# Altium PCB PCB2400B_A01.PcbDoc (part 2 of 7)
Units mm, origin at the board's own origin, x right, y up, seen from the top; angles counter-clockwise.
Board outline 115 x 60 mm, 6 copper layers (Top Layer, Signal Layer 2, Signal Layer 3, Signal Layer 4, Signal Layer 5, Bottom Layer), stack 1.555 mm thick; 382 components, 308 nets, 1384 pads, 1152 vias.
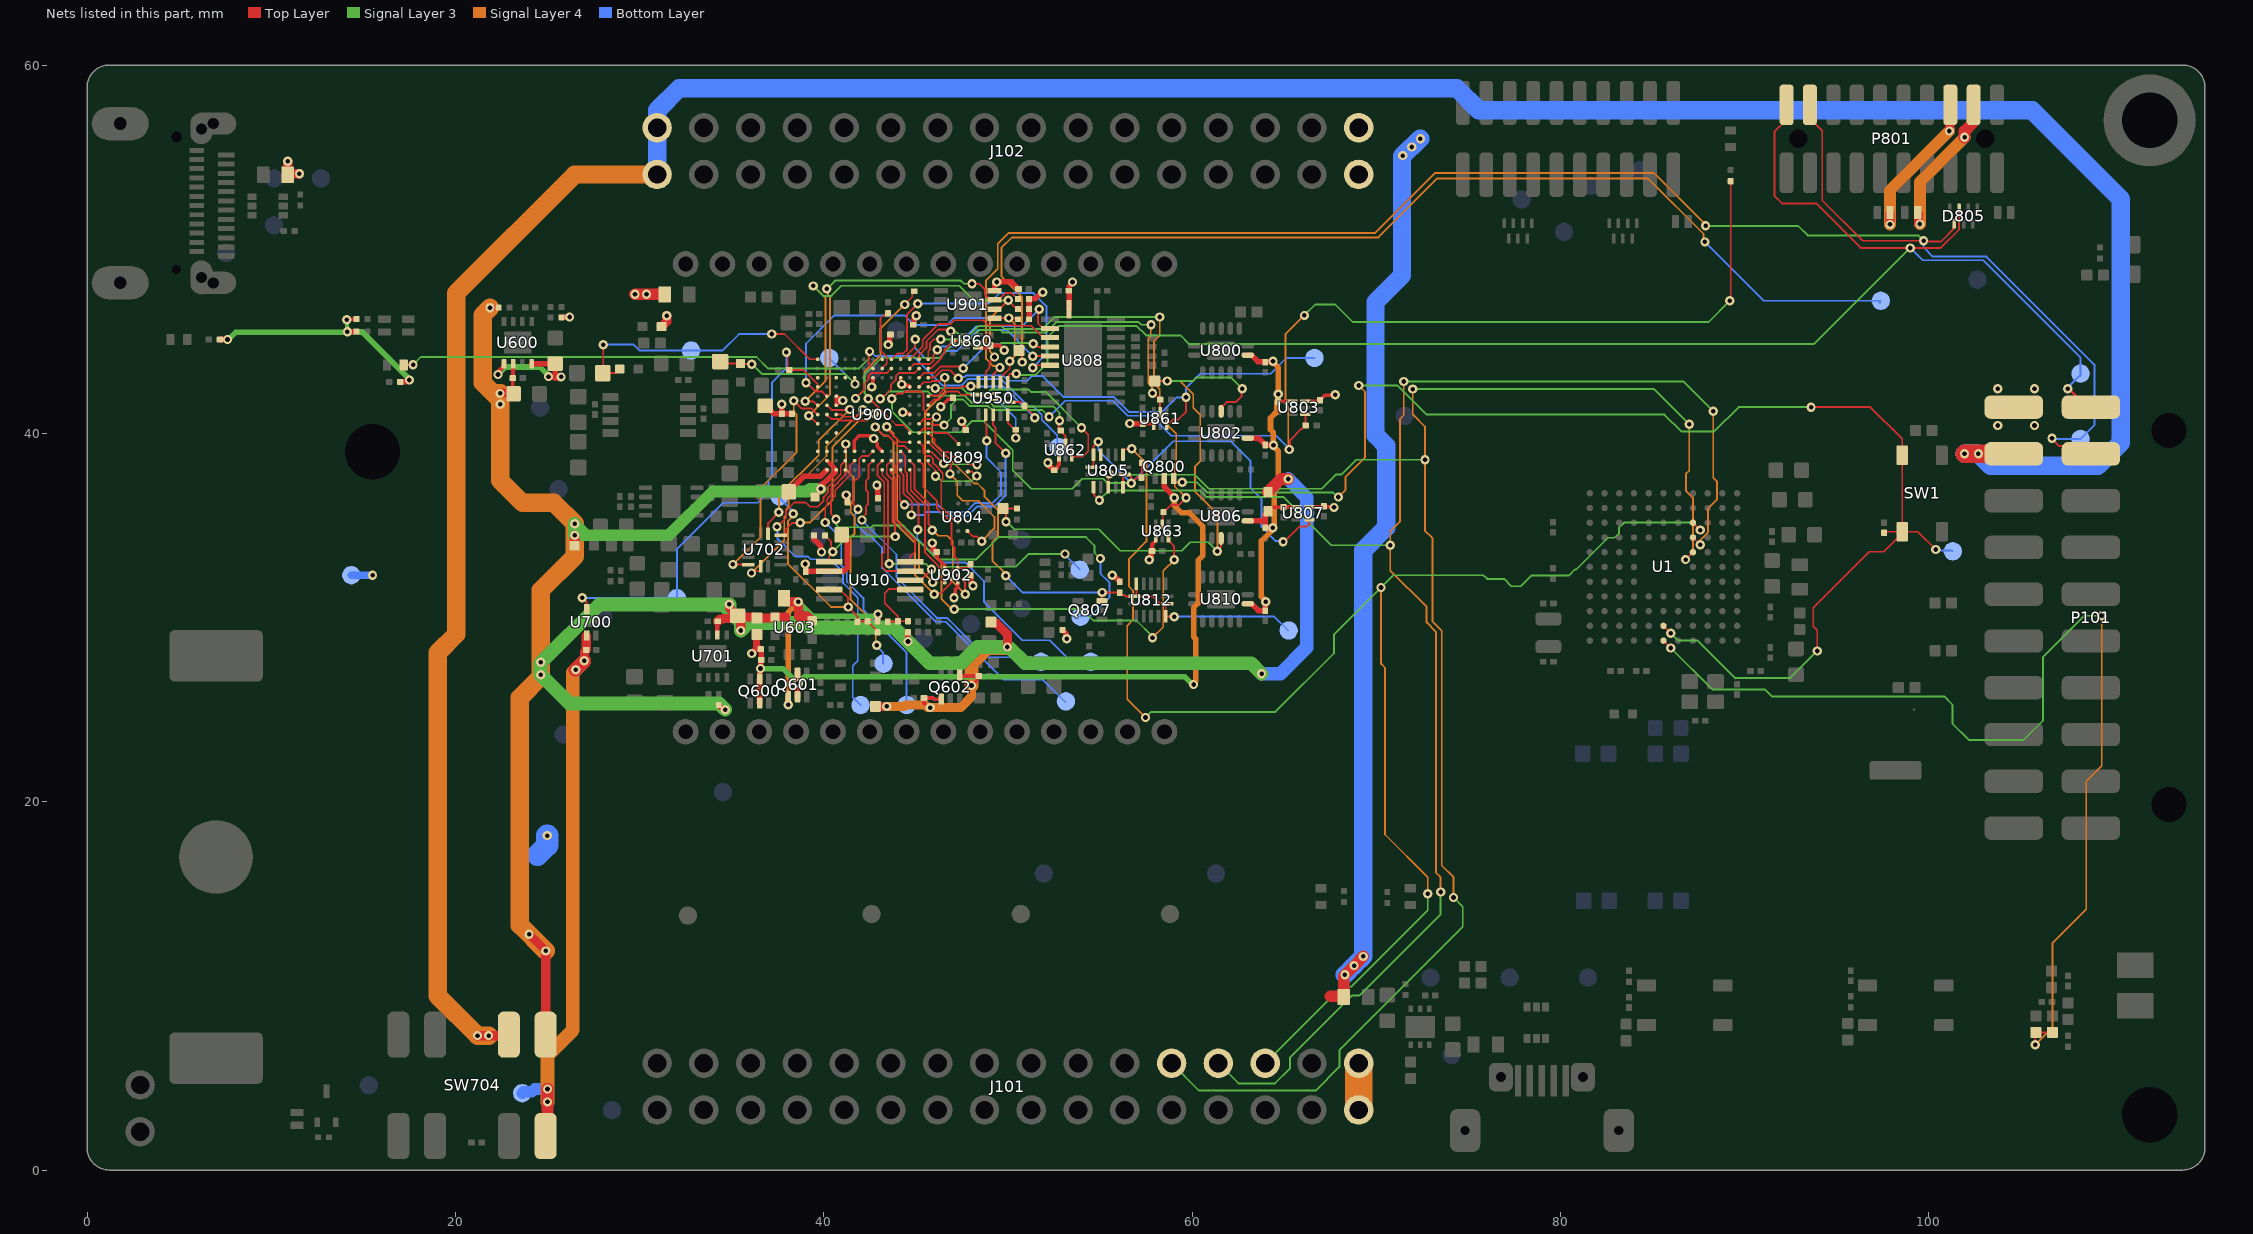
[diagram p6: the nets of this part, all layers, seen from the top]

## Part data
LED100 LED101: library part Yellow
P400: library part USB_MICRO_AB

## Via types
v1: diameter 0.5, hole 0.25, Top Layer to Bottom Layer, tented both sides, 773 vias
v2: diameter 0.508, hole 0.25, Top Layer to Bottom Layer, tented both sides, 379 vias

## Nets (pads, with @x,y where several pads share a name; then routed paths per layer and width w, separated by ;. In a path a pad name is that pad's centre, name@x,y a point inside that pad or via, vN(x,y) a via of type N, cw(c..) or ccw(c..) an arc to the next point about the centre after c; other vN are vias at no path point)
3V3: C607.1 C807.1 C808.1 C860.1 C862.1 C864.1 C866.1 C868.1 C907.1 C908.1 C909.1 C910.1 C911.1 C914.1 C921.1 C922.1 C924.1 C925.1 C926.1 C927.1 C951.1 D807.1 J101.31 J101.32 J102.31 J102.32 L704.1 L900.1 P101.20 P801.3 R601.2 R838.2 R840.2 R903.1 R906.2 R907.1 R908.1 R909.1 R912.1 R919.1 R920.1 R982.1 TPJ600.1 TPJ950.1 U600.1 U600.4 U803.6 U807.6 U808.1 U860.1 U861.1 U862.1 U863.1 U900.C6 U900.C9 U900.G3 U900.H11 U900.J11 U900.K3 U900.L4 U900.L7 U901.8 U902.A1 U902.E3 U910.2 | length 72.9
  Top Layer w0.2: v1(14.098,46.17) 14.12,46.192 14.599,46.192 R920.1@14.622,46.215 ; v2@40.8,41.775 40.8,41.65 U900.H11@40.675,41.525 U900.J11@40.675,42.025 40.72,42.025 40.958,41.787 v2(41.042,41.787) ; U900.C9@41.675,39.025 41.657,39.043 41.657,39.608 41.917,39.868 42.499,39.868 42.617,39.75 v2@42.725,39.75 ; v2(42.6,42.525) 42.659,42.584 42.659,42.802 42.675,42.818 U900.L7@42.675,43.025 ; v2(42.725,39.725) 42.725,39.642 42.904,39.462 42.904,39.296 U900.C6@43.175,39.025 ; v2(43.494,44.826) v2@43.553,44.885 ; U900.L4@44.175,43.025 44.175,42.719 v2(44.233,42.661) ; v2(44.3,41.15) 44.359,41.091 44.609,41.091 U900.G3@44.675,41.025 ; v2@44.3,42.65 44.348,42.602 44.598,42.602 U900.K3@44.675,42.525 ; C914.1@46.128,33.565 46.154,33.539 46.154,33.249 46.573,32.83 46.573,32.702 U902.A1@46.575,32.7 ; v2(46.356,41.455) 46.756,41.855 46.951,41.855 47.011,41.915 C911.1@47.011,41.935 ; v2(47.075,31.069) 47.134,31.069 47.134,31.517 47.273,31.656 47.273,31.898 U902.E3@47.275,31.9 ; v2(47.486,40.664) 47.486,40.581 47.625,40.442 47.625,40.236 47.685,40.176 C909.1@47.705,40.176 ; U860.1@48.374,44.659 48.954,44.659 49.05,44.755 C862.1@49.05,44.775 49.539,44.775 49.805,44.509 v2(49.811,44.509) ; C860.1@52.525,38 52.545,38 52.695,38.15 52.695,38.219 52.775,38.299 U862.1@52.775,38.75 ; C864.1@57.325,40.525 57.925,40.525 U861.1@57.925,40.45 ; C866.1@57.825,33.625 57.825,33.975 58.025,34.175 U863.1@58.025,34.35 ; U803.6@66.15,41.75 66.9,41.75 C807.1@66.95,41.8 66.95,41.82 67.01,41.88 67.03,41.88 67.225,42.075 67.75,42.075 v1(67.775,42.1) ; U807.6@66.38,36.01 67.126,36.01 C868.1@67.162,36.045 67.193,36.014 67.675,36.014 v1(67.707,35.982)
  Top Layer w0.254: v1(22.313,43.198) 22.36,43.245 22.36,43.383 22.637,43.659 U600.1@22.637,43.78
  Top Layer w0.3: C907.1@36.825,41.4 36.95,41.4 37.275,41.075 C924.1@37.725,41.075 ; v2(37.725,41.575) C924.1@37.725,41.075 ; C925.1@38.275,41.075 C924.1@37.725,41.075 ; v2(38.989,32.909) 39.015,32.883 39.015,32.51 C922.1@39.025,32.5 ; C922.1@39.025,32.515 39.035,32.525 41.099,32.525 41.275,32.701 41.275,34.175 C921.1@41,34.45 ; R982.1@39.471,34.452 39.481,34.452 39.491,34.442 39.491,34.231 39.837,33.885 39.837,33.601 v2(39.877,33.562) ; v2(42.889,37.179) 42.882,37.179 42.882,37.162 42.94,37.104 C926.1@42.94,36.453 ; v2@43.5,44.826 v2(43.494,44.826) 43.494,44.882 43.597,44.985 43.597,45.368 43.607,45.378 C910.1@43.627,45.378 ; C908.1@44.889,45.9 44.899,45.91 44.899,46.211 45.027,46.339 v2(45.027,46.395) ; v2(45.886,34.05) 45.875,34.05 45.875,33.994 v2@45.92,33.949 ; R906.2@47.974,32.298 47.984,32.288 47.984,31.901 48.103,31.783 v2(48.103,31.727) ; U901.8@49.275,47.75 49.275,48.1 v2(49.4,48.225) 50.2,48.225 C951.1@50.575,47.85 ; R908.1@51.15,46.2 R907.1@51.15,46.75 R909.1@51.15,47.3 51.16,47.31 51.479,47.31 51.844,47.675 v2(51.9,47.675) ; v2(52.175,38.4) 52.215,38.36 52.215,38.26 52.253,38.222 52.283,38.222 52.505,38 C860.1@52.525,38 ; R838.2@52.975,29.325 52.985,29.315 52.985,29.305 53.16,29.13 53.16,28.89 v2(53.2,28.85) ; U808.1@53.325,46.745 53.325,47.725 C808.1@53.3,47.75 53.32,47.75 53.33,47.76 53.33,47.988 53.511,48.169 v2(53.511,48.225) ; v2(55.675,32.3) 55.715,32.26 55.775,32.26 56.075,31.96 R840.2@56.075,31.95 ; v2(56.615,40.537) 56.621,40.531 57.319,40.531 C864.1@57.325,40.525 ; v2(57.675,33.143) 57.675,33.156 57.795,33.276 57.795,33.615 57.805,33.625 C866.1@57.825,33.625
  Top Layer w0.305: R903.1@7.2,45.1 v1(7.625,45.1) ; v1(14.133,45.521) 14.138,45.526 14.617,45.526 R919.1@14.622,45.531 ; R912.1@17,42.8 17.008,42.808 17.355,42.808 17.447,42.9 v1(17.5,42.9) ; U600.4@24.137,43.78 25.28,43.78 C607.1@25.3,43.8 ; v1(25.056,43.089) 25.094,43.051 25.367,43.051 25.412,43.006 ; C607.1@25.387,43.78 C607.1@25.412,43.78 ; 25.425,42.993 25.412,43.006 ; C607.1@25.437,43.78 C607.1@25.412,43.78 ; v1(25.74,43.071) 25.703,43.033 25.438,43.033 25.412,43.006 ; R601.2@25.762,46.305 25.769,46.313 26.188,46.313 v1(26.2,46.325) ; v2(41.22,36.659) 41.22,36.604 41.292,36.531 41.292,36.283 C927.1@41.3,36.275 ; v2(45.886,34.05) 45.925,34.011 45.925,33.748 46.108,33.565 C914.1@46.128,33.565 ; 25.412,43.006 C607.1@25.412,43.78
  Top Layer w0.5: L704.1@31.2,45.8 31.475,46.075 v2(31.475,46.4) ; D807.1@99.45,51.9 99.45,51.45 v1(99.525,51.375)
  Top Layer w0.635: v2(29.75,47.55) v2(30.375,47.55) L900.1@31.36,47.55 ; v2(101.95,56.075) 101.95,56.419 102.381,56.851 102.381,57.778 P801.3@102.445,57.841
  Signal Layer 3 w0.102: J101.32@69.05,5.725 J101.32@69.15,5.825
  Signal Layer 3 w0.2: v1(14.098,46.17) 14.115,46.152 14.115,45.539 v1(14.133,45.521)
  Signal Layer 3 w0.305: v1@7.625,45.05 7.628,45.05 8.078,45.5 14.133,45.5 14.3,45.5 14.289,45.51 14.939,45.51 17.55,42.9 v1@17.575,42.9 ; v1(22.313,43.198) 22.72,43.605 24.593,43.605 25.056,43.141 v1(25.056,43.089)
  Signal Layer 4 w0.635: v1(99.525,51.375) 99.525,53.65 v2(101.95,56.075)
  Signal Layer 4 w1.5: J101.31@69.05,3.262 J101.32@69.05,5.725
  Bottom Layer w0.4: TPJ600.1@14.35,32.301 15.499,32.301 v1(15.5,32.3)
  Bottom Layer w1.2: TPJ950.1@24.449,17.1 24.984,17.635 v1(24.984,18.162)
  other v1: 103.747,40.43 105.747,40.43 103.747,42.43 105.747,42.43
3V6_SW: C608.1 L702.1 Q601.1 R639.2 U603.B1 | length 14.4
  Top Layer w0.2: U603.B1@38.625,29.65 38.625,30.075
  Top Layer w0.3: Q601.1@38.075,25.7 v2(38.077,25.264) v2(38.077,25.264) ; R639.2@42.925,29.8 42.935,29.81 42.935,30.104 42.97,30.139 42.933,30.175 v2(42.947,30.189)
  Top Layer w0.5: L702.1@37.84,31.05 37.84,30.945 37.925,30.86 38.613,30.86 38.623,30.85 v2(38.625,30.85) 38.625,30.075 39.125,30.075 C608.1@39.375,29.825
  Signal Layer 3 w0.3: v2(38.625,30.85) 39.393,30.082 42.801,30.082 42.914,30.195 42.933,30.175 v2(42.947,30.189)
  Signal Layer 4 w0.3: v2(38.077,25.264) 38.077,30.302 v2(38.625,30.85)
3V6_SW_SENSE: C641.1 R639.1 R640.2 TP923.1 U910.4 | length 12.5
  Top Layer w0.1: U910.4@40.3,31.525 40.875,31.525 41.325,31.075 v2(41.325,30.575) 41.825,30.075 C641.1@41.825,29.775 41.838,29.787 42.363,29.787 R640.2@42.375,29.8 42.375,29.79 42.815,29.35 42.815,29.31 R639.1@42.925,29.2
  Signal Layer 4 w0.1: v1(38.35,35.636) 38.35,35.53 38.057,35.237 38.057,32.918 40.4,30.575 v2(41.325,30.575)
  Bottom Layer w0.1: TP923.1@37.6,36.575 37.6,36.487 38.375,35.712 38.375,35.7 38.375,35.661 v1(38.35,35.636)
5V: C600.1 C609.1 C611.1 C673.1 C674.1 C702.1 C703.1 C901.1 D806.1 L402.1 L600.2 L700.1 L800.1 P801.5 Q602.1 Q602.4 R600.2 R622.2 R633.2 R681.2 R690.2 R700.2 SW704.8 U600.2 U603.A2 U603.B2 U701.2 U900.A11 U900.B12 | length 222.3
  Top Layer w0.2: C611.1@23.1,42.2 23.145,42.155 C611.1@23.162,42.155 ; C600.1@23.112,43.005 23.112,42.238 C611.1@23.15,42.2 ; C600.1@23.125,43.025 23.124,43.026 23.124,43.768 U600.2@23.137,43.78 ; C702.1@34.225,29.775 C702.1@34.25,29.8 ; 37.925,30.025 38.106,29.844 38.106,29.777 38.225,29.658 U603.A2@38.225,29.25 ; C901.1@39.525,36.55 39.775,36.8 39.775,36.934 v2(39.834,36.993) ; U900.B12@40.175,38.525 40.325,38.375 40.325,38.35 ; C674.1@45.506,25.572 C674.1@45.446,25.632 ; v1(45.788,25.111) 45.707,25.111 45.459,25.359 45.447,25.359 C674.1@45.446,25.632 ; Q602.1@46.365,25.565 46.005,25.565 45.938,25.632 C674.1@45.446,25.632 C674.1@45.446,25.632 ; Q602.4@47.375,26.875 47.421,26.829 C673.1@48.404,26.829 ; v1(48.025,26.311) 48.344,26.63 48.344,26.769 C673.1@48.404,26.829 ; C673.1@48.424,26.829 C673.1@48.404,26.829
  Top Layer w0.25: U701.2@34.225,29.05 C702.1@34.225,29.775 ; 40.325,38.375 40.625,38.075 U900.A11@40.625,38
  Top Layer w0.3: v1(21.875,46.825) 21.878,46.828 22.334,46.828 R600.2@22.337,46.83 ; R700.2@34.3,25.25 34.3,25.24 34.499,25.041 34.609,25.041 v2(34.649,25.001) ; 40.167,37.457 40.172,37.457 ; U900.A11@40.625,37.975 40.625,37.909 40.172,37.457 ; v2(44.575,28.7) R633.2@44.575,29.2 ; v2@39.874,37.089 39.874,37.22 39.929,37.275 39.991,37.275 40.172,37.457 ; v2@39.874,37.089 39.874,37.033 v2(39.834,36.993) 39.834,37.049 v2@39.874,37.089
  Top Layer w0.5: v1(10.9,54.775) 10.9,54.06 L600.2@10.89,54.05 10.94,54.1 v1(11.525,54.1) ; v1(22.425,42.175) 22.45,42.2 C611.1@23.1,42.2 ; v1(24,12.8) v1(24.9,11.9) SW704.8@24.9,7.35 SW704.8@24.9,7.25 ; L700.1@26.475,33.9 v2(26.475,34.475) ; C702.1@34.25,29.8 34.375,29.925 34.558,29.925 34.583,29.95 35.175,29.95 C703.1@35.325,30.1 ; v2(34.875,30.725) 34.877,30.723 34.877,30.523 35.3,30.1 C703.1@35.325,30.1 ; v2(35.5,29.3) 35.498,29.302 35.498,29.95 C703.1@35.423,30.025 ; 37.925,30.025 C609.1@37.35,30.025 37.3,29.975 R622.2@36.375,29.975 36.325,30.025 C703.1@35.423,30.025 ; R681.2@42.8,25.175 v1(43.425,25.175) ; R690.2@49.075,29.75 49.125,29.7 49.365,29.7 49.973,29.092 49.973,28.402 v2(49.975,28.4) ; v1(97.9,51.35) D806.1@97.9,51.931 ; v1(101.125,56.425) 101.141,56.441 101.141,57.807 P801.5@101.175,57.841 ; C703.1@35.325,30.1 35.4,30.025 C703.1@35.423,30.025 ; C703.1@35.325,30.1 35.348,30.1 C703.1@35.423,30.025
  Top Layer w0.635: L800.1@64.125,36.825 64.825,37.525 v2(65.225,37.525) ; 67.518,9.432 68.217,9.432 L402.1@68.235,9.414 ; L402.1@68.235,9.4 L402.1@68.235,9.414 ; v1(69.3,11.6) v1(68.8,11.1) 68.235,10.535 L402.1@68.235,9.414
  Signal Layer 3 w0.635: v2(26.475,34.475) 27.1,34.475 ; v2(26.475,35.1) 27.1,34.475 ; v2(39.834,36.993) 39.251,36.993 39.107,36.849 33.969,36.849 31.595,34.475 27.1,34.475
  Signal Layer 3 w0.75: v2(26.475,34.475) v2(26.475,35.1) ; v2(34.649,25.001) 34.315,25.335 26.19,25.335 v2(24.625,26.9) 24.625,27.525 27.807,30.708 34.515,30.708 ; v2@34.875,30.708 34.515,30.708 ; v2(34.875,30.725) 34.875,30.347 ; v2(49.975,28.4) 48.35,28.4 47.475,27.525 45.75,27.525 v2(44.575,28.7) 43.818,29.457 39.134,29.457 38.891,29.7 35.9,29.7 ; v2@50.1,28.35 50.925,27.525 63.2,27.525 v2(63.775,26.95) ; 34.515,30.708 34.875,30.347 ; 34.875,30.347 35.5,29.722 35.5,29.7 ; 35.5,29.7 35.9,29.7 ; 35.5,29.7 v2(35.5,29.3) 35.9,29.7
  Signal Layer 4 w0.5: v1(43.425,25.175) 44.353,25.175 44.427,25.248 45.527,25.248 45.664,25.111 v1(45.788,25.111) 47.44,25.111 48.025,25.696 v1(48.025,26.311)
  Signal Layer 4 w0.635: v1(97.9,51.35) 97.9,53.2 v1(101.125,56.425)
  Signal Layer 4 w0.75: v1(48.025,26.311) 48.025,27.478 48.897,28.35 49.925,28.35 v2(49.975,28.4)
  Signal Layer 4 w1: v1(21.875,46.825) 21.474,46.424 21.474,42.761 22.06,42.175 ; v2(24.625,26.9) v2(24.625,27.575) 24.625,31.475 26.475,33.325 v2(26.475,34.475) ; v2@24.65,26.8 23.5,25.65 23.5,13.3 v1(24.9,11.9) ; v2@26.475,34.5 v2(26.475,35.1) 25.35,36.225 23.65,36.225 22.425,37.45 v1@22.425,41.81 ; 22.06,42.175 v1(22.425,42.175) v1@22.425,41.81 ; 22.06,42.175 v1@22.425,41.81
  Bottom Layer w0.75: v2(63.775,26.95) 64.8,26.95 66.225,28.375 66.225,36.525 v2(65.225,37.525)
  Bottom Layer w1: v1(68.3,10.6) v1(68.8,11.1) v1(69.3,11.6) 69.3,33.649 70.539,34.888 70.539,39.333 69.961,39.911 69.961,47.137 71.4,48.576 71.4,55.045 v1(71.444,55.089) 71.908,55.553 v1(71.933,55.553) 72.388,56.008 v1(72.399,56.008)
  other v1: 22.439,41.582
5V_DH_SW: C803.1 C805.1 C809.1 C827.1 C869.1 C870.1 L800.2 U800.14 U802.14 U803.1 U806.14 U807.1 U810.14 | length 23.9
  Top Layer w0.2: L800.2@64.125,35.775 64.125,35.8 64.32,35.995 C870.1@64.964,35.995 64.979,36.01 U807.1@65.68,36.01 ; C869.1@64.663,41.72 C869.1@64.687,41.745 ; v1(64.687,42.137) 64.675,42.125 64.675,41.758 C869.1@64.687,41.745 ; U803.1@65.45,41.75 64.692,41.75 C869.1@64.687,41.745
  Top Layer w0.3: U810.14@63.025,30.75 63.225,30.75 63.6,30.375 C827.1@63.975,30.375 63.985,30.385 63.985,30.841 v2(63.997,30.853) ; U806.14@63.025,35.25 63.975,35.25 ; U802.14@63.025,39.75 63.155,39.75 63.175,39.75 63.62,39.75 63.965,39.405 63.965,39.385 C805.1@63.975,39.375 63.975,39.355 63.983,39.362 64.413,39.362 v2(64.425,39.35) ; U800.14@63.025,44.25 63.225,44.25 63.57,43.905 63.965,43.905 63.975,43.895 C803.1@63.975,43.889 ; C803.1@63.975,43.875 C803.1@63.975,43.889 ; L800.2@64.125,35.775 64.125,35.75 63.975,35.6 63.975,35.25 ; v2(64.378,34.875) C809.1@63.975,34.875 63.975,35.25 ; v2(64.397,43.922) 64.374,43.899 63.985,43.899 C803.1@63.975,43.889
  Signal Layer 4 w0.3: v2(63.997,30.853) 63.997,30.909 63.77,31.136 63.77,34.17 64.339,34.739 64.339,34.835 v2(64.378,34.875) ; v2(64.397,43.922) 64.397,43.866 64.687,43.576 v1(64.687,42.137) 64.648,42.099 64.648,41.78 64.6,41.732 64.6,41.176 64.261,40.837 64.261,40.204 64.411,40.054 64.411,39.364 v2(64.425,39.35) 64.425,39.294 64.686,39.033 64.686,37.096 64.475,36.885 v2@64.475,34.875
5V_EXP: J102.1 J102.2 P101.18 SW704.7 | length 168.8
  Top Layer w0.508: v1(21.2,7.3) v1(21.8,7.3) 22.85,7.3 SW704.7@22.9,7.25
  Top Layer w1: v1(101.949,38.9) 101.949,38.89 P101.18@104.747,38.89
  Signal Layer 4 w1: v1(21.8,7.3) v1(21.2,7.3) 19.044,9.456 19.044,28.094 20.034,29.084 20.034,47.609 26.487,54.062 J102.1@30.95,54.062
  Bottom Layer w1: J102.1@30.95,54.062 J102.2@30.95,56.602 30.96,56.612 30.96,57.547 32.163,58.75 74.369,58.75 75.573,57.546 105.615,57.546 110.43,52.731 110.43,39.486 109.185,38.241 103.359,38.241 v1(102.7,38.9) v1(101.949,38.9)
5V_SENSE: C635.1 R633.1 R634.2 U910.7 | length 4.4
  Top Layer w0.1: C635.1@43.475,29.775 43.488,29.787 44.013,29.787 R634.2@44.025,29.8 ; R633.1@44.575,29.8 R634.2@44.025,29.8 ; U910.7@44.7,31.525 44.679,31.546 43.54,31.546 43.31,31.316 43.31,30.79 44.025,30.075 R634.2@44.025,29.8
5V_SW: C610.1 Q600.2 Q600.5 Q601.2 Q601.5 Q800.5 R622.1 R623.2 | length 43.4
  Top Layer w0.3: Q601.2@38.575,25.7 38.575,26.375 v2@38.575,26.424 ; Q601.5@38.575,27 v2@38.575,26.424 ; v2(38.624,26.424) v2@38.575,26.424 ; Q800.5@58.5,37.55 58.5,37.111 58.61,37.001 58.61,36.971 59.025,36.556 v2(59.025,36.5)
  Top Layer w0.305: v2(36.092,28.052) 36.092,28.073 36.299,28.279 ; R622.1@36.375,29.075 R622.1@36.375,28.909 ; Q600.2@36.513,25.36 Q600.5@36.513,26.66 36.515,26.662 36.515,27.127 36.567,27.179 v2(36.567,27.234) 36.587,27.254 36.587,27.694 36.595,27.702 C610.1@36.607,27.702 36.607,28.272 36.592,28.287 R623.2@36.582,28.287 ; 36.299,28.279 36.299,28.833 R622.1@36.375,28.909 ; 36.299,28.279 36.574,28.279 R623.2@36.582,28.287 ; R622.1@36.375,28.909 36.375,28.484 36.572,28.287 R623.2@36.582,28.287
  Signal Layer 3 w0.3: v2(36.567,27.234) 37.799,27.234 38.61,26.424 v2(38.624,26.424) ; v2@38.527,26.384 38.944,26.8 59.594,26.8 60.026,26.368 v2(60.082,26.368)
  Signal Layer 4 w0.3: v2(59.025,36.5) 59.025,36.079 59.423,35.681 59.866,35.681 60.593,34.954 60.593,33.365 60.332,33.104 60.332,30.782 60.086,30.536 60.086,28.954 60.193,28.847 60.193,26.535 60.082,26.424 v2(60.082,26.368)
#RESET: R805.2 R809.1 R810.2 U802.4 U806.11 | length 33
  Top Layer w0.1: v2(49.9,35.2) 49.9,35.75 R810.2@49.725,35.925 R809.1@50.5,35.925 ; R805.2@57.975,42.85 57.98,42.845 v2(58.644,42.845) ; v2(61.375,33.6) 61.375,33.647 61.575,33.847 U806.11@61.575,34.3 ; U802.4@61.575,41.2 61.575,41.4 61.875,41.7 62.381,41.7 62.694,42.014 62.694,42.38 v2(62.732,42.418)
  Signal Layer 3 w0.1: v2(49.9,35.2) 49.95,35.2 50.356,34.794 54.931,34.794 56.1,33.625 59.431,33.625 59.899,34.093 60.882,34.093 v2(61.375,33.6) ; v2(58.644,42.845) 60.039,42.845 60.237,43.043 62.107,43.043 v2(62.732,42.418)
  Signal Layer 4 w0.1: v2(58.644,42.845) 59.358,42.845 60.066,42.136 60.066,41.389 60.443,41.013 60.443,38.485 60.157,38.199 60.157,36.856 61.375,35.638 v2(61.375,33.6)
AEM_5V_#ENABLE: U900.L10
AEM_CALIBRATE0: U702.13 U900.G11 | length 13.7
  Top Layer w0.1: v2(36.075,32.421) 36.185,32.421 36.284,32.52 36.525,32.52 36.575,32.57 U702.13@36.575,32.79 ; U900.G11@40.675,41.025 40.957,41.025 41.076,40.906 41.757,40.906 v2(42.127,41.277)
  Signal Layer 4 w0.1: v2@36.176,32.499 36.176,32.522 37.857,34.203 37.857,35.472 37.953,35.567 37.953,35.856 38.082,35.986 38.082,36.707 40.15,38.775 40.15,39.3 v2(42.127,41.277)
AEM_CALIBRATE1: U702.5 U900.G12 | length 12.5
  Top Layer w0.1: U702.5@37.66,34.475 37.88,34.475 37.93,34.525 37.93,34.786 38.287,35.143 38.705,35.143 v2(38.718,35.156) ; U900.G12@40.175,41.025 40.425,40.775 40.875,40.775 40.943,40.706 42.381,40.706 v2(42.75,41.075)
  Signal Layer 4 w0.1: v2(38.718,35.156) 39.249,35.156 40.473,36.38 40.473,39.254 41.937,40.718 42.393,40.718 v2(42.75,41.075)
AEM_CALIBRATE2: U702.6 U900.H12 | length 9.9
  Top Layer w0.1: U702.6@36.975,34.56 36.975,35.133 37.552,35.711 v2(37.552,35.722) ; U900.H12@40.175,41.525 40.425,41.275 41.381,41.275 v2(41.405,41.299)
  Signal Layer 4 w0.1: v2(37.552,35.722) 37.563,35.734 37.563,36.663 39.725,38.825 39.725,39.619 v2(41.405,41.299)
AEM_CALIBRATE3: U702.12 U900.G13 | length 12.8
  Top Layer w0.1: v2(35.069,32.886) 35.089,32.886 35.095,32.881 35.884,32.881 U702.12@35.89,32.875 ; v2@38.4,41.725 38.425,41.725 38.8,41.35 39.35,41.35 U900.G13@39.675,41.025
  Signal Layer 4 w0.1: v2(35.069,32.886) 35.089,32.886 36.566,34.363 36.566,37.014 38.525,38.973 38.525,41.025 38.375,41.175 v2(38.375,41.775)
AEM_CURRENT_HIGH_GAIN: C720.1 R764.2 TP706.1 U900.N13 | length 15.3
  Top Layer w0.1: v2(28.025,44.825) 28.025,43.3 R764.2@28,43.275 28.7,43.275 C720.1@28.925,43.5 ; v2(37.175,45.4) 37.868,45.4 39.243,44.025 U900.N13@39.675,44.025
  Bottom Layer w0.1: v2(28.025,44.825) 29.675,44.825 30,44.5 TP706.1@32.8,44.5 34.5,44.5 35.4,45.4 v2(37.175,45.4)
AEM_CURRENT_LOW_GAIN: C724.1 R768.2 TP707.1 U900.L9 | length 10.2
  Top Layer w0.1: R768.2@34.375,43.9 34.475,43.8 35.425,43.8 C724.1@35.475,43.8 35.5,43.775 36.1,43.775 v2(36.1,43.757) ; U900.L9@41.675,43.025 41.686,43.014 41.686,42.697 v2(41.697,42.686)
  Signal Layer 3 w0.1: v2(36.1,43.757) 36.109,43.766 36.65,43.225 41.158,43.225 v2(41.697,42.686)
  Bottom Layer w0.1: TP707.1@40.3,44.1 40.3,44.091 41.697,42.695 v2(41.697,42.686)
AEM_SENSE_SELECT: U900.L13
AEM_SWITCH_POS: U900.L11
AEM_VMCU: C708.1 SW704.4 TP709.1 U700.1 | length 31
  Top Layer w0.5: v2(27,27.65) 27.002,27.652 27.002,28.152 C708.1@27.1,28.25 U700.1@27.1,29
  Top Layer w0.635: SW704.4@24.9,1.75 25,1.85 v1(25,3.7) v1(25,4.4)
  Top Layer w0.75: v2(26.525,27.175) v2(27,27.65)
  Signal Layer 4 w0.75: v1(25,3.7) v1(25,4.4) 25,6.225 26.375,7.6 26.375,27.025 v2(27,27.65)
  Bottom Layer w0.635: TP709.1@23.625,4.175 23.695,4.245 24.145,4.245 24.3,4.4 v1(25,4.4)
AEM_VMCU_ENABLE: R763.2 TP715.1 U700.4 U900.K13 | length 25.7
  Top Layer w0.1: v2(26.888,31.087) 27.125,30.85 U700.4@27.125,30.475 ; v2(37.975,44.407) 38.05,44.332 38.05,43.525 R763.2@38.125,43.45 38.896,43.45 39.671,42.675 39.671,42.529 U900.K13@39.675,42.525
  Bottom Layer w0.1: v2@27.05,31.041 27.077,31.068 32.007,31.068 TP715.1@32.025,31.05 32.025,33.712 34.547,36.234 36.428,36.234 36.988,36.793 cw(c37.6,36.575) 37.003,36.833 37.003,37.472 37.188,37.656 37.188,42.763 37.975,43.55 v2(37.975,44.407)
BC_ADC_SPI_CIPO: U900.B6 U910.9 | length 7.7
  Top Layer w0.1: U900.B6@43.175,38.525 42.925,38.275 42.925,37.709 43.282,37.352 43.282,33.549 43.164,33.431 43.164,32.762 43.401,32.525 U910.9@44.7,32.525
BC_ADC_SPI_COPI: U900.A6 U910.8 | length 9.1
  Top Layer w0.1: U900.A6@43.175,38.025 43.175,37.742 43.482,37.434 43.482,33 v2(43.557,32.925) ; U910.8@44.7,32.025 45.275,32.025 45.85,32.6 v2(45.85,32.625)
  Signal Layer 3 w0.1: v2(43.557,32.925) 45.55,32.925 v2(45.85,32.625)
BC_ADC_SPI_CS: R982.2 U900.B5 U910.1 | length 9.8
  Top Layer w0.1: R982.2@40.071,34.452 40.081,34.452 40.392,34.141 40.392,33.984 40.406,33.97 40.406,33.662 v2(40.484,33.584) 40.484,33.509 40.4,33.425 40.3,33.325 U910.1@40.3,33.025 ; U900.B5@43.675,38.525 43.425,38.275 43.425,37.79 43.725,37.49 43.725,35.192 43.875,35.042 v2(43.875,34.4)
  Signal Layer 3 w0.1: v2(40.484,33.584) 40.484,33.586 41.298,34.4 v2(43.875,34.4)
BC_ADC_SPI_SCLK: U900.A5 U910.10 | length 5.6
  Top Layer w0.1: U900.A5@43.675,38.025 43.675,37.823 43.925,37.573 43.925,35.275 44.964,34.236 44.964,33.589 44.7,33.325 U910.10@44.7,33.025
BC_BUTTON_ENABLE: R981.1 U900.H1 U950.6 U950.12 | length 8.2
  Top Layer w0.1: U900.H1@45.675,41.525 45.998,41.848 46.287,41.848 46.59,42.152 46.59,42.169 46.621,42.2 46.701,42.28 47.273,42.28 47.453,42.1 U950.6@48.315,42.1 48.365,42.05 49.2,42.05 v2(49.25,42) ; U950.12@50,41.015 50,40.578 50.268,40.31 50.315,40.31 R981.1@50.425,40.2 v2(50.425,39.75)
  Bottom Layer w0.1: v2(49.25,42) 50.425,40.825 v2(50.425,39.75)
BC_DAC_OUT: U900.N6
BC_DBG_#RESET: LED903.1 TPJ956.1 U900.M7 | length 40.6
  Top Layer w0.1: LED903.1@17.189,43.71 17.204,43.725 v1(17.7,43.725) ; v2(42.489,44.45) 42.45,44.45 42.425,44.425 42.425,43.775 U900.M7@42.675,43.525
  Signal Layer 3 w0.1: v1(17.7,43.725) 18.125,44.15 21.343,44.15 36.35,44.15 36.968,43.532 41.932,43.532 42.45,44.05 42.45,44.45 v2(42.489,44.45)
  Bottom Layer w0.1: v2(42.489,44.45) 42.56,44.45 42.81,44.2 44.856,44.2 46.455,42.601 47.464,42.601 47.813,42.95 49.633,42.95 51.112,41.471 51.384,41.471 51.843,41.013 51.843,40.737 52.68,39.9 52.68,39.32 TPJ956.1@52.75,39.25
BC_DBG_TCK_SWCLK: TPJ954.1 U900.C10 | length 13.4
  Top Layer w0.1: U900.C10@41.175,39.025 41.188,39.038 41.188,39.288 v2@41.175,39.3
  Signal Layer 4 w0.1: v2(41.2,39.425) 41.2,38.046 41.613,37.633 41.613,36.34 41.466,36.193 41.466,35.712 41.613,35.565 41.613,35.543 41.668,35.488 41.668,34.544 41.45,34.327 41.45,31.006 42.823,29.632 42.823,28.685 42.878,28.631 42.878,28.502 v1(42.873,28.498)
  Bottom Layer w0.1: v1(42.873,28.498) 42.873,28.445 43.226,28.091 43.226,27.524 TPJ954.1@43.25,27.5
BC_DBG_TDO_SWO: TPJ955.1 U900.A10 | length 15.3
  Top Layer w0.1: v2(40.083,35.163) 40.083,36 40.193,36.11 40.193,36.464 40.427,36.698 40.427,37.005 ; 40.611,37.188 40.427,37.005 ; U900.A10@41.175,38.025 41.175,37.752 40.427,37.005
  Bottom Layer w0.1: v2@40.125,35.2 40.125,35.121 40.95,34.296 40.95,32.85 41.25,32.55 41.25,31.958 41.275,31.933 42.15,31.058 42.15,30.431 44.5,28.081 TPJ955.1@44.5,25.25
BC_DBG_TMS_SWDIO: TPJ953.1 U900.B10 | length 19
  Top Layer w0.1: v2(37.464,34.932) 37.956,35.424 37.956,35.806 38.4,36.25 39.025,36.25 39.257,36.018 39.676,36.018 39.993,36.335 39.993,36.546 40.227,36.78 40.227,37.087 40.925,37.785 40.925,38.275 U900.B10@41.175,38.525
  Bottom Layer w0.1: v2(37.464,34.932) 37.495,34.901 37.495,34.271 38.449,33.317 39.137,33.317 39.285,33.169 40.331,33.169 41.05,32.45 41.05,31.85 ; 41.075,31.85 41.85,31.075 41.85,27.65 41.575,27.375 41.575,25.675 TPJ953.1@42,25.25
BC_DISP_COM: U900.E11
BC_DISP_PWR_ENABLE: U900.D12
BC_DISP_SPI_COPI: U900.B8
BC_DISP_SPI_CS: U900.C12
BC_DISP_SPI_SCLK: U900.C13
BC_I2C_EXP_ENABLE: R950.1 U900.J1 U950.5 U950.13 | length 9.1
  Top Layer w0.1: U900.J1@45.675,42.025 45.694,42.044 45.911,42.044 45.924,42.057 46.213,42.057 46.39,42.234 46.39,42.252 46.618,42.48 47.405,42.48 47.482,42.557 48.35,42.557 48.4,42.607 U950.5@48.4,42.785 ; U950.13@50.085,41.7 50.71,41.7 50.9,41.51 50.9,41.49 51.45,40.94 v2(51.45,40.85)
  Bottom Layer w0.1: v2(47.976,42.557) 49.743,42.557 v2(51.45,40.85)
BC_I2C_EXP_SCL: D805.5 P101.17 P801.17 TPJ651.1 U950.3 | length 96.3
  Top Layer w0.1: U950.3@49.2,42.785 49.213,42.798 49.213,43.213 49.568,43.568 v2(49.568,43.582) ; P801.17@93.525,57.825 93.525,57.148 94.225,56.448 94.225,52.65 96.414,50.461 v1(99.725,50.461) ; v1@99.802,50.423 100.673,50.423 101.355,51.105 101.355,51.34 D805.5@101.4,51.385 ; v1(106.7,39.739) 106.7,39.702 107.092,39.31 107.296,39.31 107.51,39.096 107.51,38.89 P101.17@108.557,38.89
  Signal Layer 3 w0.1: v1(87.885,51.273) 92.905,51.273 93.428,50.75 99.436,50.75 v1@99.693,50.493
  Signal Layer 4 w0.1: v2(49.568,43.582) 49.497,43.653 49.216,43.653 48.82,44.049 48.82,48.318 49.45,48.948 49.45,50.3 50.031,50.881 69.931,50.881 73.2,54.15 85.075,54.15 87.885,51.34 v1(87.885,51.273)
  Bottom Layer w0.1: v1(99.725,50.461) 99.733,50.461 99.733,50.1 100.233,49.6 103.135,49.6 109,43.735 109,40.452 TPJ651.1@108.248,39.7 ; v1(106.7,39.739) 106.738,39.701 TPJ651.1@108.247,39.701
BC_I2C_EXP_SDA: D805.3 P101.19 P801.19 TPJ650.1 U950.1 | length 88.3
  Top Layer w0.1: U950.1@50,42.785 50.05,42.835 50.05,43.162 50.109,43.22 50.42,43.22 v2(50.45,43.25) ; P801.19@92.285,57.841 92.285,57.047 91.625,56.387 91.625,52.9 92.036,52.489 93.886,52.489 96.303,50.072 v1(99,50.072) 99,50.075 99.561,50.075 99.564,50.072 99.886,50.072 99.889,50.075 100.651,50.075 101.65,51.074 D805.3@101.65,52.215
  Top Layer w0.127: P101.19@107.557,41.422 107.585,41.45 P101.19@107.605,41.43 ; v1@107.6,42.6 107.6,42.439 108.609,41.43 109.496,41.43 P101.19@109.557,41.491
  Signal Layer 3 w0.1: v2@50.45,43.35 50.618,43.182 51.513,43.182 52.143,43.813 52.143,45.21 52.776,45.843 56.982,45.843 57.504,45.321 59.373,45.321 59.833,44.861 93.789,44.861 v1(99,50.072)
  Bottom Layer w0.1: v1(99,50.072) v1(99,50.072) 99.675,49.4 102.959,49.4 108.248,44.11 TPJ650.1@108.248,43.251
  Bottom Layer w0.127: v1(107.557,42.43) 107.557,42.495 TPJ650.1@108.248,43.186 ; TPJ650.1@108.248,43.121 TPJ650.1@108.248,43.186 ; TPJ650.1@108.248,43.251 TPJ650.1@108.248,43.186
BC_SPI_CIPO: U900.B3 U902.C3 | length 10
  Top Layer w0.1: U900.B3@44.675,38.525 44.925,38.275 44.925,36.999 45.541,36.383 45.693,36.231 45.693,35.067 45.9,34.86 v2(45.9,34.75) ; U902.C3@47.275,32.3 47.675,31.9 v2(47.675,31.275)
  Signal Layer 4 w0.1: v2(45.9,34.75) 46.207,34.443 46.713,34.443 47.007,34.149 47.007,31.943 v2(47.675,31.275)
BC_SPI_COPI: U900.C3 U902.D2 | length 14.4
  Top Layer w0.1: v2(42.8,40.35) 43.278,39.872 43.51,39.872 44.057,39.325 44.375,39.325 U900.C3@44.675,39.025 ; v2(45.994,31.269) 46.072,31.347 46.383,31.347 46.904,31.868 46.904,32.079 U902.D2@46.925,32.1
  Signal Layer 4 w0.1: v2(42.8,40.35) 43.267,39.883 43.499,39.883 43.792,39.59 43.792,35.208 44.964,34.036 44.964,32.3 v2(45.994,31.269)
BC_SPI_CS: R906.1 U900.B2 U902.A3 | length 7.5
  Top Layer w0.1: U900.B2@45.175,38.525 45.425,38.275 45.425,37.064 46.147,36.342 46.147,35.934 46.943,35.138 46.943,33.957 47.109,33.791 47.109,33.31 47.275,33.144 U902.A3@47.275,32.7 47.786,32.7 47.974,32.888 R906.1@47.974,32.898
BC_SPI_SCLK: U900.A3 U902.E1 | length 6.9
  Top Layer w0.1: U900.A3@44.675,38.025 44.675,38.009 44.725,37.959 44.725,36.916 45.493,36.148 45.493,33.538 45.766,33.265 46.243,32.788 46.243,32.232 U902.E1@46.575,31.9
BC_TRACECLK: TPJ957.1 U900.B7 | length 17.2
  Top Layer w0.1: v2(42.075,35.3) 42.075,35.41 42.294,35.63 42.294,36.041 42.4,36.147 42.4,36.823 42.289,36.934 42.289,37.414 42.296,37.421 42.296,37.425 42.425,37.553 42.425,38.275 U900.B7@42.675,38.525
  Bottom Layer w0.1: v2(42.075,35.3) 43.95,33.425 43.95,32.192 46.167,29.975 46.713,29.975 47.021,29.668 47.368,29.321 48.842,27.846 51.308,27.846 51.555,27.599 TPJ957.1@51.799,27.599
BC_TRACED0: TPJ958.1 U900.C7 | length 20.8
  Top Layer w0.1: v2(41.859,35.875) 41.614,36.12 41.614,37.339 41.925,37.65 41.925,38.629 42.071,38.775 42.425,38.775 U900.C7@42.675,39.025
  Bottom Layer w0.1: v2(41.859,35.875) 41.859,35.765 41.682,35.588 41.682,35.137 42.351,34.468 42.495,34.468 43.164,33.799 43.164,32.695 46.084,29.775 46.631,29.775 49.781,26.625 51.9,26.625 TPJ958.1@53.1,25.425
BC_TRACED1: TPJ959.1 U900.C4 | length 17.9
  Top Layer w0.1: U900.C4@44.175,39.025 44.425,38.775 44.425,37.921 44.525,37.821 44.525,36.833 45.141,36.217 45.141,34.816 v2(45.1,34.775)
  Bottom Layer w0.1: v2(45.1,34.775) 45.075,34.75 45.075,34.294 46.369,33 47.683,33 48.696,31.987 48.696,30.855 50.783,28.768 52.277,28.768 53.446,27.599 54.176,27.599 TPJ959.1@54.325,27.45
BC_TRACED2: TPJ960.1 U900.D3 | length 20.1
  Top Layer w0.1: v2(43.423,40.368) 43.501,40.29 43.501,40.173 44.149,39.525 U900.D3@44.675,39.525
  Signal Layer 3 w0.1: v2@45.975,31.975 46.757,32.757 50.424,32.757 51.117,33.45 v1(53.1,33.45)
  Signal Layer 4 w0.1: v2(43.423,40.368) 43.785,40.007 43.785,39.88 43.992,39.673 43.992,35.291 45.164,34.119 45.164,32.686 v2(45.925,31.925)
  Bottom Layer w0.1: v1(53.1,33.45) 53.1,33.424 53.899,32.625 TPJ960.1@53.899,32.598
BC_TRACED3: TPJ961.1 U900.B9 | length 25
  Top Layer w0.1: v2(40.667,35.337) 40.667,35.36 40.393,35.634 40.393,36.381 40.627,36.615 40.627,36.922 ; 40.752,37.046 40.627,36.922 ; U900.B9@41.675,38.525 41.425,38.275 41.425,37.719 40.627,36.922
  Signal Layer 3 w0.1: v2(40.667,35.337) 40.656,35.325 40.656,35.065 40.814,34.907 42.58,34.907 42.666,34.993 44.326,34.993 46.162,33.157 48.286,33.157 49.506,34.377 54.238,34.377 54.704,33.911 54.704,33.532 v1(55.026,33.21)
  Bottom Layer w0.1: TPJ961.1@53.95,30.05 54.016,30.116 54.541,30.116 55.509,31.084 55.509,31.91 55.026,32.393 v1(55.026,33.21)
BC_UIF_BUTTON0: U900.B4 U950.9 | length 13.2
  Top Layer w0.1: U900.B4@44.175,38.525 43.925,38.275 43.925,37.856 44.125,37.656 44.125,36.394 v2(44.385,36.135) ; U950.9@48.8,41.015 48.8,40.46 48.844,40.416 v2(48.844,39.604)
  Bottom Layer w0.1: v2(44.385,36.135) 46.197,36.135 46.599,35.732 47.744,35.732 48.237,36.225 49.181,36.225 49.625,36.669 49.625,37.894 48.844,38.675 v2(48.844,39.604)
BC_UIF_BUTTON1: U900.A4 U950.10 | length 13.1
  Top Layer w0.1: U900.A4@44.175,38.025 44.184,38.016 44.184,37.88 44.325,37.739 44.325,36.75 44.687,36.388 44.8,36.275 44.8,35.65 44.813,35.637 v1(44.752,35.575) ; U950.10@49.2,41.015 49.2,40.455 49.335,40.32 49.335,39.465 v2(49.875,38.925)
  Bottom Layer w0.1: v1(44.752,35.575) 44.8,35.575 45.425,35.575 45.577,35.727 46.321,35.727 46.516,35.532 47.826,35.532 48.319,36.025 49.263,36.025 49.875,36.637 v2(49.875,38.925)
BC_VCOM_CTS: U863.3 U900.K2 | length 33
  Top Layer w0.1: U900.K2@45.175,42.525 45.425,42.775 45.819,42.775 45.887,42.843 46.271,42.843 46.464,43.036 v2(46.575,43.036) ; U863.3@58.725,34.35 58.725,34.175 59.025,33.875 v2(59.025,33.143)
  Signal Layer 3 w0.1: v2(47.078,30.461) 54.022,30.461 54.64,29.843 56.985,29.843 57.85,28.977 v2(57.85,28.9)
  Signal Layer 4 w0.1: v2(46.575,43.036) 46.575,42.23 45.493,41.148 45.493,33.876 46.387,32.982 46.387,31.017 47.01,30.394 v2(47.078,30.461) ; v2(57.85,28.9) 58.437,29.488 58.437,32.538 59.025,33.125 v2(59.025,33.143)
BC_VCOM_CTS_DIR: R853.2 U863.5 U900.N2 | length 27.7
  Top Layer w0.1: U900.N2@45.175,44.025 45.175,44.242 45.575,44.642 45.575,44.992 46.226,45.643 46.697,45.643 46.79,45.55 v2(46.9,45.55) ; U863.5@58.375,35.05 58.412,35.087 58.412,35.688 R853.2@58.45,35.725 58.46,35.725 58.842,36.107 59.282,36.107 v2(59.675,36.5)
  Signal Layer 3 w0.1: v2(46.9,45.55) 46.978,45.472 47.252,45.472 47.365,45.359 47.934,45.359 48.393,45.818 49.658,45.818 49.802,45.675 51.9,45.675 52.55,46.325 v2(58.25,46.325)
  Signal Layer 4 w0.1: v2(58.25,46.325) 58.25,45.336 57.932,45.018 57.932,42.718 58.243,42.408 58.243,40.876 59.143,39.976 59.143,38.449 59.057,38.363 59.057,37.118 v2(59.675,36.5)
BC_VCOM_ENABLE: Q807.3 R840.1 TP930.1 U812.5 U812.6 U812.12 U812.13 U900.F2 | length 30.1
  Top Layer w0.1: U900.F2@45.175,40.525 45.425,40.775 45.779,40.775 45.825,40.821 46.052,40.821 v2(46.124,40.893) ; Q807.3@55.1,30.9 55.116,30.916 v2(55.116,31.366) ; v2@55.125,31.35 55.133,31.358 56.067,31.358 R840.1@56.075,31.35 56.075,31.34 56.185,31.23 56.32,31.23 56.4,31.15 U812.13@56.89,31.15 57.856,31.15 58.238,30.768 58.557,30.768 U812.6@58.575,30.75 ; U812.13@56.925,31.15 56.975,31.2 U812.12@56.975,31.835 ; U812.6@58.66,30.75 U812.6@58.575,30.75 ; v2(59.025,30.05) 58.59,30.05 U812.5@58.575,30.065 U812.6@58.575,30.75
  Signal Layer 4 w0.1: v2(46.124,40.893) 46.124,40.875 45.889,40.64 45.889,39.559 48.166,37.282 48.349,37.282 48.732,36.899 48.732,36.562 49.468,35.826 49.468,34.409 49.158,34.099 49.158,33.092 49.878,32.373 v2(49.878,32.277)
  Bottom Layer w0.1: v2(49.878,32.277) 50.788,31.366 v2(55.116,31.366) ; v2(59.025,30.05) 61.702,30.05 64.466,30.05 TP930.1@65.216,29.3
BC_VCOM_RTS: U862.3 U900.K1 | length 11.9
  Top Layer w0.1: U900.K1@45.675,42.525 45.694,42.506 45.994,42.506 v2(46.05,42.45) ; U862.3@53.475,38.75 54.081,38.75 54.368,39.037 54.368,39.939 v2(53.997,40.31)
  Signal Layer 3 w0.1: v2(46.05,42.45) 47.527,42.45 47.813,42.164 48.859,42.164 49.087,42.393 51.101,42.393 51.237,42.257 52.05,42.257 v2(53.997,40.31)
BC_VCOM_RTS_DIR: R852.2 U862.5 U900.M2 | length 15.3
  Top Layer w0.1: v2(43.075,41.875) 43.131,41.875 43.654,42.398 43.654,42.652 43.777,42.775 43.779,42.775 43.901,42.898 43.901,42.9 43.921,42.92 43.923,42.944 43.925,42.987 43.925,43.013 43.925,43.129 44.071,43.275 44.925,43.275 U900.M2@45.175,43.525 ; v2(52.802,40.68) 52.75,40.627 52.75,40.25 53.125,39.875 U862.5@53.125,39.45
  Signal Layer 3 w0.1: v2(43.075,41.875) 43.131,41.875 43.524,42.268 45.676,42.268 45.901,42.043 47.652,42.043 48.013,41.681 49.013,41.681 49.223,41.471 52.454,41.471 52.802,41.123 v2(52.802,40.68)
BC_VCOM_RXD: R882.2 TPJ606.1 U900.L2 | length 67
  Top Layer w0.1: U900.L2@45.175,43.025 45.425,43.275 45.975,43.275 46.329,43.629 47.371,43.629 47.465,43.536 v2(47.575,43.536) ; R882.2@50.6,44.5 50.775,44.325 v2(50.775,43.875)
  Signal Layer 4 w0.1: v2(50.775,43.875) 50.775,47.406 49.65,48.531 49.65,50.075 50.223,50.648 70.123,50.648 73.325,53.85 84.758,53.85 87.774,50.834 87.774,50.476 v1(87.85,50.4)
  Bottom Layer w0.1: v2(47.575,43.536) 48.871,44.832 49.576,44.832 49.646,44.902 50.273,44.902 50.775,44.4 v2(50.775,43.875) ; v1@87.875,50.375 91.049,47.201 TPJ606.1@97.4,47.201 97.299,47.1 TPJ606.1@97.4,47.1
BC_VCOM_RXD_DIR: R850.2 U860.5 U900.M1 | length 2.8
  Top Layer w0.1: U900.M1@45.675,43.525 45.694,43.544 45.831,43.544 46.4,44.114 46.4,44.214 46.561,44.375 46.561,44.556 47.007,45.002 R850.2@47.007,45.012 47.009,45.01 47.673,45.01 U860.5@47.674,45.009
BC_VCOM_TXD: TPJ607.1 U861.3 U900.L1 | length 26.1
  Top Layer w0.1: U900.L1@45.675,43.025 45.693,43.043 46.026,43.043 46.412,43.429 46.864,43.429 v2(47.3,42.994) ; U861.3@58.625,40.45 58.625,40.541 58.675,40.591 58.816,40.591 58.984,40.759 59.264,40.759 59.674,41.168 v2(59.674,41.974)
  Bottom Layer w0.1: v2@47.304,42.996 47.38,43.072 47.652,43.072 47.73,43.15 49.716,43.15 50.009,42.857 51.051,42.857 51.304,43.11 51.89,43.11 53.025,41.975 55.769,41.975 56.587,41.157 58.357,41.157 59,41.8 59.157,41.957 59.657,41.957 v2(59.674,41.974) 59.674,42.479 60.437,43.243 64.274,43.243 65.131,44.1 TPJ607.1@66.65,44.1
BC_VCOM_TXD_DIR: R851.2 U861.5 U900.N1 | length 18.6
  Top Layer w0.1: U900.N1@45.675,44.025 45.675,44.459 45.775,44.559 45.775,44.909 45.981,45.116 v2(46.361,45.116) ; v2(57.85,42.175) 57.919,42.175 58.262,41.832 R851.2@58.272,41.832 ; U861.5@58.275,41.15 R851.2@58.275,41.8
  Signal Layer 3 w0.1: v2@46.4,45.1 47.958,45.1 48.476,45.618 49.576,45.618 49.719,45.475 52.05,45.475 52.618,46.043 57.107,46.043 57.25,45.9 v1(57.775,45.9)
  Signal Layer 4 w0.1: v1(57.775,45.9) 57.759,45.884 57.759,45.284 57.625,45.15 57.625,42.725 57.83,42.52 57.83,42.195 v2(57.85,42.175)
BOARD_ID_SCL: R907.2 U900.H13 U901.6 U950.4 | length 26
  Top Layer w0.1: v2(38.991,41.743) 39.43,41.743 39.648,41.525 U900.H13@39.675,41.525 ; U950.4@48.8,42.785 48.8,43.344 48.998,43.543 48.998,43.855 49.275,44.132 v2(49.275,44.15) ; U901.6@49.275,46.75 49.375,46.85 49.65,46.85 v2(50.026,47.226) ; v2@50.007,47.23 50.378,46.86 50.44,46.86 R907.2@50.55,46.75
  Signal Layer 3 w0.1: v2(39.44,48.009) 39.977,47.472 40.416,47.472 40.962,48.018 47.357,48.018 48.149,47.226 v2(50.026,47.226)
  Signal Layer 4 w0.1: v2(38.991,41.743) 40.1,42.852 40.1,47.349 v2(39.44,48.009) ; v2(49.275,44.15) 49.275,44.211 49.02,44.466 49.02,46.22 v2(50.026,47.226)
BOARD_ID_SDA: R908.2 U900.J12 U901.5 U950.2 | length 21
  Top Layer w0.1: v2(39.038,42.753) 39.06,42.775 39.56,42.275 39.925,42.275 U900.J12@40.175,42.025 ; U901.5@49.275,46.25 49.284,46.259 49.988,46.259 v2@50.051,46.196 ; U950.2@49.6,42.785 49.6,43.025 49.75,43.175 ; 49.75,43.175 50.1,43.525 v2(50.1,43.925) ; v2(50.051,46.268) v2@50.051,46.196 ; R908.2@50.55,46.2 50.516,46.234 50.089,46.234 v2@50.051,46.196
  Signal Layer 4 w0.1: v2(50.051,46.268) 50.375,45.944 50.375,44.2 v2(50.1,43.925)
  Bottom Layer w0.1: v2(39.038,42.753) 39.038,44.874 40.577,46.413 44.387,46.413 44.918,45.882 46.676,45.882 47.062,46.268 v2(50.051,46.268)
BOARD_ID_WP: R909.2 U900.F13 U901.7 | length 19.6
  Top Layer w0.1: v2(39.187,40.957) 39.216,40.957 39.648,40.525 U900.F13@39.675,40.525 ; v2(48.05,48.125) 48.45,48.125 48.75,47.825 48.75,47.55 49.05,47.25 49.5,47.25 49.633,47.383 49.633,47.389 49.863,47.619 50.221,47.619 50.54,47.3 R909.2@50.55,47.3
  Signal Layer 3 w0.1: v2(40.162,47.865) 40.185,47.865 40.62,48.3 47.45,48.3 47.625,48.125 v2(48.05,48.125)
  Signal Layer 4 w0.1: v2(39.187,40.957) 40.344,42.114 40.344,47.387 40.24,47.492 40.24,47.787 v2(40.162,47.865)
BOARD_VER0: R930.1 U900.M5 | length 10.2
  Top Layer w0.1: v2(41.725,41.9) 42.187,42.362 42.187,42.684 42.425,42.921 42.425,43.129 42.571,43.275 43.425,43.275 U900.M5@43.675,43.525 ; v2@44.365,47 v2(44.4,47) 44.808,47.408 44.808,47.613 R930.1@44.913,47.718
  Signal Layer 4 w0.1: v2(41.725,41.9) 42.207,42.382 42.207,43.357 43.075,44.225 43.075,45.675 44.325,46.925 v2@44.325,47.075
BOARD_VER1: R931.1 U900.M6 | length 3.5
  Top Layer w0.1: U900.M6@43.179,43.529 43.425,43.775 43.425,44.175 43.075,44.525 43.075,46.24 43.248,46.413 43.376,46.413 R931.1@43.484,46.521
DAC_LC_EXCITE: R198.1 R300.1 U1.L6 | length 57.8
  Top Layer w0.1: U1.L6@85.599,28.752 85.601,28.751 v1(86.001,28.349) ; v1(105.786,6.8) 105.786,7.436 R300.1@105.825,7.475 R198.1@106.722,7.475
  Signal Layer 3 w0.1: v1(86.001,28.349) 88.247,26.102 91.105,26.102 91.485,25.722 100.838,25.722 101.295,25.265 101.295,24.246 102.186,23.355 105.155,23.355 106.211,24.411 106.211,27.861 108.45,30.1 v1(109.4,30.1)
  Signal Layer 4 w0.1: v1(105.786,6.8) 106.722,7.736 106.722,12.322 108.557,14.157 108.557,21.11 109.4,21.953 v1(109.4,30.1)
DBG_VREGO: C902.1 U900.A12 | length 2.7
  Top Layer w0.12: U900.A12@40.16,38.01 U900.A12@40.19,38.01
  Top Layer w0.3: C902.1@38.019,36.819 38.069,36.819 38.925,37.675 39.82,37.675 40.145,38 U900.A12@40.15,38
DEBUG_#RESET_C2CKPS: C8.1 Q800.6 SW1.1 SW1.2 TP400.1 U1.K6 | length 76.5
  Top Layer w0.1: Q800.6@59,37.55 59,37.45 59.1,37.35 v2(59.475,37.35) ; U1.K6@85.6,29.55 v1(86.001,29.149) ; v1(93.618,41.427) 96.84,41.427 98.567,39.7 SW1.2@98.567,38.814 SW1.1@98.567,34.664 ; v1(93.951,28.188) 93.951,29.313 93.735,29.529 93.735,30.535 96.779,33.579 97.565,33.579 SW1.1@98.601,34.614 ; C8.1@97.601,34.614 97.65,34.664 SW1.1@98.567,34.664 ; SW1.1@98.631,34.6 SW1.1@98.567,34.664 ; v1(100.386,33.696) 99.418,34.664 98.601,34.664 SW1.1@98.567,34.664
  Signal Layer 3 w0.1: v2(59.475,37.35) 60.262,37.35 60.817,36.794 67.629,36.794 67.873,36.55 v1(67.95,36.55) ; v1@69.061,42.6 71.172,42.6 72.747,41.025 85.65,41.025 86.564,40.111 88.361,40.111 89.677,41.427 v1(93.618,41.427) ; v1(86.001,29.149) 86.401,28.749 87.451,28.749 89.5,26.7 89.511,26.711 92.488,26.711 92.547,26.77 92.547,26.784 v1(93.951,28.188)
  Signal Layer 4 w0.1: v1(67.95,36.55) 68.335,36.935 68.335,37.045 68.326,37.054 68.326,37.626 69.4,38.7 69.4,42.25 v1(69.05,42.6)
  Bottom Layer w0.1: v1(100.386,33.696) 100.434,33.648 101.263,33.648 TP400.1@101.312,33.599
DEBUG_#RESET_IN: U808.7 U900.N5 | length 16
  Top Layer w0.1: U900.N5@43.675,44.025 43.991,44.341 44.321,44.341 44.525,44.545 44.525,46.475 v2(45.1,47.05) ; v2(51.35,43.575) 51.46,43.575 51.585,43.7 U808.7@52.28,43.7
  Bottom Layer w0.1: v2(45.1,47.05) 48.975,47.05 49.544,47.619 51.384,47.619 52.092,46.911 52.092,44.317 v2(51.35,43.575)
DEBUG_DH_SW_ENABLE: R817.2 R900.1 U803.4 U900.F1 | length 63.4
  Top Layer w0.1: U900.F1@45.675,40.525 45.936,40.525 46.011,40.45 v1(46.534,40.45) ; v2(65.281,39.125) 65.325,39.169 65.325,39.636 65.937,40.248 65.972,40.248 66.16,40.436 R817.2@66.17,40.436 66.17,41.03 U803.4@66.15,41.05 ; v1(89.203,47.2) 89.25,47.247 R900.1@89.25,53.7
  Signal Layer 3 w0.1: v1(46.534,40.45) 46.912,40.827 46.912,41.542 47.212,41.843 47.569,41.843 47.93,41.481 48.93,41.481 49.14,41.271 51.864,41.271 v2(52.236,40.9) ; v1(66.1,46.407) 66.693,47 67.777,47 68.727,46.05 88.053,46.05 v1(89.203,47.2)
  Signal Layer 4 w0.1: 65.075,41.976 65.075,41.6 65.221,41.454 65.221,39.185 v2(65.281,39.125) ; 65.076,41.976 65.076,42.351 65.072,42.355 65.072,45.379 v1(66.1,46.407)
  Bottom Layer w0.1: v2(52.236,40.9) 53.111,41.775 55.687,41.775 56.504,40.957 57.793,40.957 58.875,39.875 64.575,39.875 65.281,39.169 v2(65.281,39.125)
DEBUG_MCU_SW_ENABLE: R814.2 R815.2 U805.5 U805.6 U805.12 U805.13 U807.4 U900.G1 | length 42.8
  Top Layer w0.1: v2(43.7,41.875) 43.993,42.168 44.296,42.168 44.403,42.275 45.279,42.275 45.425,42.129 45.425,41.275 U900.G1@45.675,41.025 ; U805.13@54.565,38.17 54.6,38.17 54.65,38.22 54.65,39.334 54.859,39.544 v2(54.907,39.544) ; U805.5@56.25,37.085 56.25,37.72 56.3,37.77 56.575,37.77 56.636,37.709 56.641,37.709 56.7,37.65 v2(56.7,37.3) 57,37.6 R814.2@57.254,37.6 ; R814.2@57.275,37.6 R815.2@57.275,38.406 ; v1(64.944,34.119) 65.011,34.119 65.844,34.952 66.225,34.952 66.38,35.107 U807.4@66.38,35.31
  Signal Layer 3 w0.1: v2(43.7,41.875) 43.7,41.194 44.833,40.061 47.438,40.061 48.045,40.668 48.688,40.668 50.268,39.088 50.268,37.995 51.264,36.999 53.489,36.999 54.033,37.543 55.19,37.543 55.433,37.3 v2(56.7,37.3)
  Bottom Layer w0.1: v2(54.907,39.544) 54.907,39.093 v2(56.7,37.3) 58.973,39.573 62.1,39.573 63.168,38.505 63.168,37.038 63.774,36.432 63.774,34.924 64.544,34.154 64.909,34.154 v1(64.944,34.119)
DEBUG_RESET_#OE: U804.A1 U900.D1 | length 8.8
  Top Layer w0.1: U900.D1@45.707,39.518 45.707,39.493 46.426,38.774 46.673,38.774 46.914,38.534 46.914,38.208 46.888,38.182 46.888,37.834 v2(46.854,37.8) ; U804.A1@47.8,34.7 48.088,34.412 48.312,34.412 48.574,34.15 v2(48.575,34.15)
  Signal Layer 4 w0.1: v2(46.854,37.8) 47.25,37.404 47.25,36.643 47.548,36.345 48.386,36.345 49.268,35.463 49.268,34.843 v2(48.575,34.15)
DEBUG_TCK_SWCLK_#OE: U809.A1 U900.B1 | length 4.1
  Top Layer w0.1: U900.B1@45.675,38.525 45.679,38.521 45.679,38.375 46.068,37.986 v2(46.068,37.673) ; U809.A1@47.825,37.925 48.05,37.925 48.286,37.689 v2(48.314,37.689)
  Signal Layer 3 w0.1: v2(46.068,37.673) 46.068,37.636 46.178,37.636 46.407,37.407 47.996,37.407 48.264,37.675 48.3,37.675 v2(48.314,37.689)
DEBUG_TCK_SWCLK_C2CK: J101.24 U1.E8 U805.3 | length 93.8
  Top Layer w0.1: U805.3@55.45,37.085 55.45,37.75 v2(55.5,37.8) ; v1@86.85,33.2 U1.E8@87.2,33.55
  Signal Layer 3 w0.1: v2(55.5,37.8) 55.543,37.757 60.137,37.757 60.9,36.994 67.035,36.994 67.803,37.762 68.101,37.762 68.913,38.574 v1(72.648,38.574) ; J101.24@58.89,5.802 60.379,4.313 66.713,4.313 68,5.6 68,6.5 74.7,13.2 74.7,14.3 v1(74.2,14.8) ; v1(71.983,42.405) 85.095,42.405 v1(87,40.5)
  Signal Layer 4 w0.1: v1(71.983,42.405) 71.983,41.042 72.648,40.377 72.648,34.727 73.05,34.325 73.05,29.8 73.563,29.287 73.563,16.537 74.2,15.9 v1(74.2,14.8) ; v1@86.85,33.2 87.2,33.55 87.2,36.5 87.194,36.506 87.194,36.513 86.819,36.888 86.819,37.8 87,37.981 v1(87,40.5)
  other v1: 86.8,33.15
DEBUG_TCK_SWCLK_IN: U808.4 U900.N3 | length 9.1
  Top Layer w0.1: U900.N3@44.675,44.025 45.375,44.725 45.375,45.075 46.25,45.95 46.9,45.95 47.095,46.145 48.66,46.145 48.93,45.875 50.408,45.875 50.433,45.85 51.275,45.85 51.925,45.2 U808.4@52.28,45.2
DEBUG_TCK_SWCLK_OUT: U809.B1 U900.C1 | length 3.6
  Top Layer w0.1: U900.C1@45.675,39.025 45.694,39.006 45.844,39.006 46.495,38.355 46.51,38.371 v2(46.521,38.371) ; U809.B1@47.825,38.425 47.95,38.3 v2(48.325,38.3)
  Signal Layer 3 w0.1: v2(46.521,38.371) 46.495,38.345 46.517,38.322 48.303,38.322 v2(48.325,38.3)
DEBUG_TDI_#OE: U809.B2 U900.E1 | length 2.4
  Top Layer w0.1: U900.E1@45.675,40.025 46.007,39.693 46.007,39.476 46.483,39 46.75,39 U809.B2@47.325,38.425
DEBUG_TDI_C2DPS: U805.11
DEBUG_TDI_IN: U808.6 U900.N4 | length 10.7
  Top Layer w0.1: U900.N4@44.175,44.025 44.202,44.025 44.318,44.141 44.404,44.141 44.966,44.703 v2(44.966,45.107) ; v2(51.35,44.2) U808.6@52.28,44.2
  Bottom Layer w0.1: v2(44.966,45.107) 44.966,44.634 45.489,44.111 46.297,44.111 46.661,44.475 47.233,44.475 48.376,45.618 49.932,45.618 v2(51.35,44.2)
DEBUG_TDI_OUT: U809.D2 U900.E2 | length 2.6
  Top Layer w0.1: U900.E2@45.175,40.025 45.425,40.275 45.779,40.275 46.029,40.025 46.721,40.025 47.321,39.425 U809.D2@47.325,39.425
DEBUG_TDO_SWO: J101.28 U1.C8 U805.8 | length 84.1
  Top Layer w0.1: U805.8@56.25,38.855 56.25,39.075 56.3,39.125 56.3,39.145 56.695,39.145 v2(56.725,39.175) ; U1.C8@87.2,35.15 v1(87.601,34.75)
  Signal Layer 3 w0.1: v1(57.475,24.575) 57.775,24.875 64.525,24.875 67.7,28.05 67.7,29.072 70.928,32.3 75.825,32.3 76.025,32.1 76.942,32.1 77.342,31.7 77.842,31.7 78.42,32.278 80.453,32.278 80.786,32.611 80.861,32.611 82.588,34.338 82.94,34.338 83.19,34.589 83.19,34.892 83.459,35.161 87.19,35.161 v1(87.601,34.75) ; J101.28@63.97,5.802 68.118,9.95 68.65,9.95 72.8,14.1 v1(72.8,15)
  Signal Layer 4 w0.1: v2(56.725,39.175) 57.525,38.375 57.525,34.133 56.582,33.19 56.582,31.67 56.793,31.459 56.793,29.877 56.479,29.563 56.479,25.571 57.45,24.6 v1@57.45,24.575 ; v1(70.263,31.635) 70.263,27.486 70.479,27.27 70.479,18.221 72.8,15.9 v1(72.8,15)
DEBUG_TDO_SWO_IN: U808.5 U900.E3 | length 15.3
  Top Layer w0.1: v2(42.425,41.875) 42.506,41.875 43.924,40.457 44.328,40.457 44.57,40.215 44.656,40.129 44.656,40.044 U900.E3@44.675,40.025 ; v2(51.375,44.875) 51.46,44.875 51.635,44.7 U808.5@52.28,44.7
  Signal Layer 3 w0.1: v2(42.425,41.875) 42.425,41.985 42.207,42.203 42.207,43.182 43.136,44.111 46.297,44.111 47.019,44.832 49.576,44.832 49.646,44.902 51.348,44.902 v2(51.375,44.875)
DEBUG_TMS_SWDIO_#OE: U804.B2 U900.D2 | length 5.5
  Top Layer w0.1: U900.D2@45.175,39.525 45.425,39.275 45.425,38.921 45.571,38.775 45.779,38.775 45.925,38.629 45.925,38.411 46.125,38.211 46.268,38.068 46.268,38.029 46.461,37.836 46.461,37.798 46.461,37.473 46.382,37.394 46.382,35.987 47.147,35.222 47.278,35.222 U804.B2@47.3,35.2
DEBUG_TMS_SWDIO_C2D: J101.26 U1.D8 U805.1 | length 90.9
  Top Layer w0.1: U805.1@54.65,37.085 54.672,37.063 54.672,36.667 v2(54.971,36.368) ; U1.D8@87.2,34.35 v1(87.601,33.95)
  Signal Layer 3 w0.1: v2(54.971,36.368) 54.971,36.39 55.474,36.893 60.436,36.893 60.779,36.55 64.943,36.55 67.563,33.93 v1(70.767,33.93) ; J101.26@61.43,5.802 62.532,4.7 64.5,4.7 65.325,5.525 65.325,6.125 68.675,9.475 69.075,9.475 73.5,13.9 v1(73.5,15.1) ; v1(71.5,42.822) 86.678,42.822 v1(88.3,41.2)
  Signal Layer 4 w0.1: v1(71.5,42.822) 71.5,41 71.3,40.8 71.3,35.225 70.767,34.692 v1(70.767,33.93) 70.767,32.553 72.738,30.582 72.738,29.736 73.244,29.23 73.244,16.156 73.5,15.9 v1(73.5,15.1) ; v1(87.601,33.95) 87.601,34.193 88.012,34.604 88.012,35.907 88.5,36.395 88.5,37.397 88.3,37.597 v1(88.3,41.2)
DEBUG_TMS_SWDIO_IN: U808.3 U900.M3 | length 10.1
  Top Layer w0.1: U900.M3@44.675,43.525 44.925,43.775 45.779,43.775 45.967,43.964 45.967,44.275 46.168,44.476 v2(46.168,44.537) ; v2(51.699,46.748) 51.635,46.684 51.635,45.99 51.925,45.7 U808.3@52.28,45.7
  Bottom Layer w0.1: v2(46.168,44.537) 46.245,44.537 46.433,44.725 47.2,44.725 48.293,45.818 50.769,45.818 v2(51.699,46.748)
